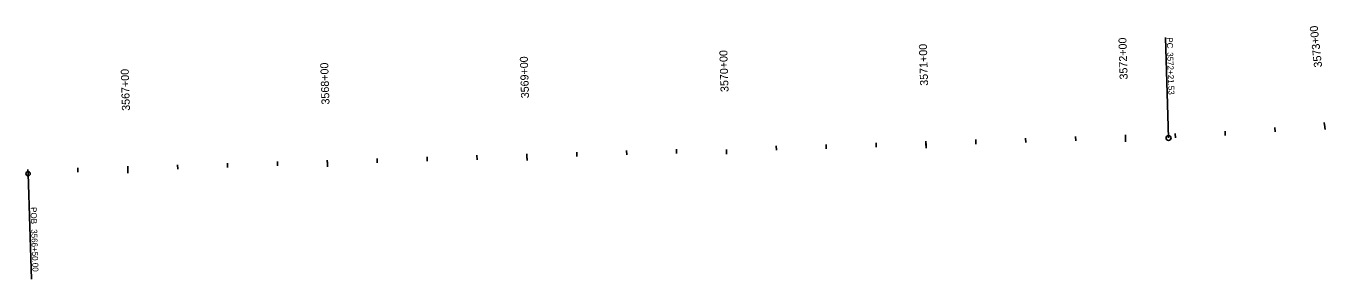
# Model space of a CAD drawing. Extents: x 19570301 to 19572259, y 7727180 to 7727858.
# Drawn here: x 19570301 to 19570951, y 7727180 to 7727307 of the extents above; entities that cross this region are included whole.
import ezdxf

# ---------------------------------------------------------------- set-up
doc = ezdxf.new("R2010")
doc.units = 0
for name, color, linetype in [('Alignment', 7, 'Continuous'), ('SheetText', 7, 'Continuous'), ('Terrain', 7, 'Continuous')]:
    doc.layers.add(name, color=color, linetype=linetype)

msp = doc.modelspace()

# ---------------------------------------------------------------- linework, layer by layer
at = {"layer": 'Alignment'}
for p, q in [((19570872.89, 7727250.74), (19570871.31, 7727301.12)), ((19570871.31, 7727301.12), (19570871.31, 7727301.12)), ((19570301.64, 7727232.8), (19570303.3, 7727180.03)), ((19570303.3, 7727180.03), (19570303.3, 7727180.03))]:
    msp.add_line(p, q, dxfattribs=at)
for centre, radius in [((19570872.89, 7727250.74), 1.25), ((19570301.64, 7727232.8), 1.07)]:
    msp.add_circle(centre, radius, dxfattribs=at)
at = {"layer": 'SheetText'}
for p, q in [((19570951.15, 7727256.28), (19570950.91, 7727258.45)), ((19570851.37, 7727250.07), (19570851.3, 7727252.25)), ((19570551.52, 7727240.65), (19570551.45, 7727242.83)), ((19570651.43, 7727245.01), (19570651.51, 7727242.56)), ((19570751.42, 7727246.93), (19570751.35, 7727249.11)), ((19570351.62, 7727234.37), (19570351.55, 7727236.55)), ((19570451.57, 7727237.51), (19570451.5, 7727239.69))]:
    msp.add_line(p, q, dxfattribs=at)
at = {"layer": 'Terrain'}
for p, q in [((19570926.27, 7727253.85), (19570926.08, 7727256.02)), ((19570951.01, 7727257.5), (19570951.28, 7727255.06)), ((19570776.41, 7727247.71), (19570776.34, 7727249.89)), ((19570801.4, 7727248.5), (19570801.33, 7727250.68)), ((19570826.38, 7727249.28), (19570826.32, 7727251.46)), ((19570851.33, 7727251.29), (19570851.41, 7727248.84)), ((19570876.36, 7727250.86), (19570876.28, 7727253.04)), ((19570901.33, 7727252.04), (19570901.2, 7727254.22)), ((19570576.51, 7727241.43), (19570576.44, 7727243.62)), ((19570601.5, 7727242.22), (19570601.43, 7727244.4)), ((19570626.48, 7727243), (19570626.41, 7727245.19)), ((19570651.43, 7727245.01), (19570651.51, 7727242.56)), ((19570676.46, 7727244.57), (19570676.39, 7727246.76)), ((19570701.45, 7727245.36), (19570701.38, 7727247.54)), ((19570726.43, 7727246.14), (19570726.37, 7727248.33)), ((19570751.38, 7727248.15), (19570751.46, 7727245.7)), ((19570376.61, 7727235.15), (19570376.54, 7727237.34)), ((19570401.59, 7727235.94), (19570401.53, 7727238.12)), ((19570426.58, 7727236.72), (19570426.51, 7727238.91)), ((19570451.53, 7727238.73), (19570451.61, 7727236.29)), ((19570476.56, 7727238.29), (19570476.49, 7727240.48)), ((19570501.55, 7727239.08), (19570501.48, 7727241.26)), ((19570526.53, 7727239.86), (19570526.46, 7727242.05)), ((19570551.48, 7727241.87), (19570551.56, 7727239.43)), ((19570301.64, 7727232.8), (19570301.58, 7727234.98)), ((19570326.63, 7727233.58), (19570326.56, 7727235.77)), ((19570351.58, 7727235.59), (19570351.66, 7727233.15))]:
    msp.add_line(p, q, dxfattribs=at)

# ---------------------------------------------------------------- texts
at = {"layer": 'Alignment'}
for s, p in [('PC', (19570871.97, 7727301.14)), ('3572+21.53', (19570872.2, 7727293.67)), ('POB ', (19570302.83, 7727216.03)), ('3566+50.00', (19570303.18, 7727204.95))]:
    msp.add_text(s, height=3, rotation=271.79899, dxfattribs=at).set_placement(p)
at = {"layer": 'SheetText'}
msp.add_text('3570+00', height=4.008, rotation=91.79899, dxfattribs=at).set_placement((19570652.53, 7727273.84))
at = {"layer": 'Terrain'}
for s, rotation, p in [('3573+00', 96.29499, (19570949.85, 7727286.32)), ('3571+00', 91.79899, (19570752.48, 7727276.98)), ('3572+00', 91.79899, (19570852.43, 7727280.11)), ('3568+00', 91.79899, (19570452.63, 7727267.56)), ('3569+00', 91.79899, (19570552.58, 7727270.7)), ('3570+00', 91.79899, (19570652.53, 7727273.84)), ('3567+00', 91.79899, (19570352.68, 7727264.42))]:
    msp.add_text(s, height=4.008, rotation=rotation, dxfattribs=at).set_placement(p)

doc.saveas('drawing.dxf')
